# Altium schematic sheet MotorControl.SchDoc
size A
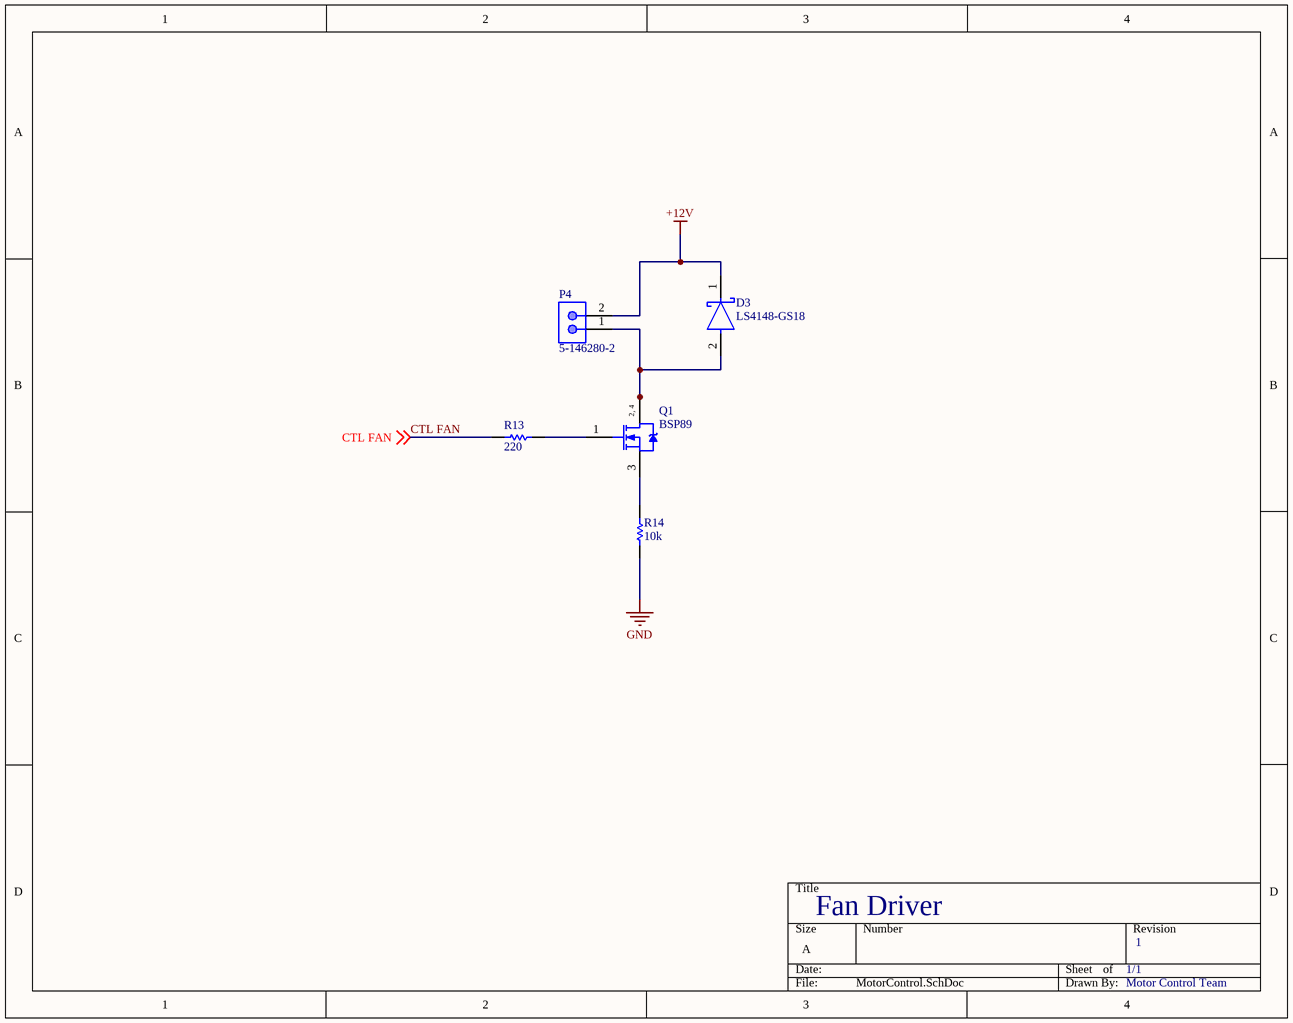
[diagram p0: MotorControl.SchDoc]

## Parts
D3  LS4148-GS18  [FP-6_560-5006_01-4-MFG]
P4  5-146280-2  [TECO-5-146280-2_V]
Q1  BSP89  [INF-PG-SOT223_SC-73_M]
R13  value 220  [RESC2013X70X40ML20T20]  (hidden comment: Resistor 1k +/-1% 0805 125 mW)
R14  value 10k  [RESC2013X70X40ML20T20]  (hidden comment: Resistor 1k +/-1% 0805 125 mW)

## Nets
+12V: D3.1(C) P4.2
GND: R14.1
CTL FAN: R13.2 ; off-sheet CTL FAN
NetD3_2: D3.2(A) P4.1 Q1.2(DRAIN) Q1.4(DRAIN)
NetQ1_1: Q1.1(GATE) R13.1
NetQ1_3: Q1.3(SOURCE) R14.2

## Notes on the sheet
- Fan Driver
- 1/1
- 1
- Motor Control Team

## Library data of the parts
D3 = CMP-02539-000014-1: DIODE GEN PURP 75V 150MA SOD80; Manufacturer: Vishay; Capacitance: 4pF; Max Surge Forward Current: 2A; Forward Current: 300mA; Max Repetitive Reverse Voltage: 100V; Max Junction Temp: +175°C; Peak Reverse Current: 5uA; Value: 4pF; Automotive Grade: Grade 0
P4 = CMP-2000-07492-1: Male Header, Pitch 2.54 mm, 1 x 2 Position, Height 8.21 mm, Tail Length 3.05 mm, -65 to 105 degC, RoHS, Bulk; Manufacturer: TE Connectivity; Mating Connector Lock: No(Without); Number of Positions: 2; Pitch: 2.54mm; PCB Mounting Orientation: Vertical; Keyed: No; Case\/Package: 100; Mating Post Length: 0.23inch; High Temperature Housing: Yes; Max Current Rating: 5A; PCB Thickness: 0.063inch; PCB Mount Retention: Without; Approvals: CSA; Current Rating: 3A
Q1 = CMP-1149-00010-1: N-Channel SIPMOS Small-Signal-Transistor, 240 V VDS, 0.35 A ID, -55 to 150 degC, PG-SOT223 (SC-73), Reel, Green; Manufacturer: Infineon; Polarity: N; Ptot (max): 1.8Â W; RDS (on) (max) (@4.5V): 7,500 mOhm; ID (max): 0.35Â A; Mode: Enhancement; VDS (max): 240 V; RthJA (max): 115 K/W; VGS(th) (min): 0.8Â V; RDS (on) (max): 6,000 mOhm; QG: 4.3Â nC; VGS(th) (max): 1.8Â V; IDpuls (max): 1.4Â A; Green: TRUE
R13 R14 = CMP-009-00010-4: Chip Resistor, 1 KOhm, +/- 1%, 0.125 W, -55 to 155 degC, 0805 (2013 Metric); Power: 125mW; Voltage Rating: 150V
